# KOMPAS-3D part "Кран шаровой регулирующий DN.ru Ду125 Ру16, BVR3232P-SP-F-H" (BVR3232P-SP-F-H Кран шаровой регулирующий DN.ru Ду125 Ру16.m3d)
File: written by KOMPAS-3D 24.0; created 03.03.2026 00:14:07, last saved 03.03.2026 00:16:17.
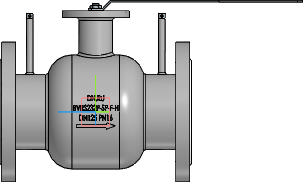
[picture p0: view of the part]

Document properties: Автор: Максим; Полное имя файла: BVR3232P-SP-F-H - Кран шаровой регулирующий DN.ru  Ду125 Ру16.cdw

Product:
- Body: Тело 1  | qty 1
    Масса: 46.599159
- Part/product: Кран шаровой регулирующий DN.ru Ду125 Ру16  | designation BVR3232P-SP-F-H
    Масса: 26.2
    Раздел спецификации: Прочие изделия
    Форматы листов документа: A2
    Примечание: D160-69426

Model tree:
1. Операция без истории:1

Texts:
  BVR3232P-SP-F-H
